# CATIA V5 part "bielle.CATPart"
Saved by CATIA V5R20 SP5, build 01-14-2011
Part number: bielle
Publications: "epaisseur"
Bounding box of the stored display mesh (mm): x -125 to 350, y 175.015 to 450.797, z 445 to 928.333
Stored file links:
  F:\iao fini\bielle.CATPart
  F:\iao fini\iao-finipbgliss.CATProduct
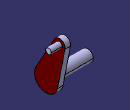
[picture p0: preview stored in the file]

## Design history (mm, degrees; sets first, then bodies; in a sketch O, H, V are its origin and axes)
Parameters
  epaisseur = 50 mm
External parameters (linked from other documents)
  External.rayontrou = 50 mm
  External.epaisseur = 125 mm
Set1
  Plane1 "Planbielle": linked copy from another document
  Point1 "Abis": linked copy from another document
  Point2: linked copy from another document
Body1 (main body)
  Sketch1 on Plane1, origin (200, 0, 0), H (0, 1, 0), V (0, 0, 1)
    arc A1 centre (400.9199, 878.4484) radius 49.8847 from (449.8633, 868.8035) to (357.4062, 902.842) ccw
    point P1 (400.9199, 878.4484)
    arc A2 centre (280, 550) radius 105.019 from (188.3935, 601.3542) to (383.0374, 529.6951) ccw
    point P2 (280, 550)
    reference projected point E1 (280, 550) from Point1
    reference projected point E2 (400.9199, 878.4484) from Point2
    line L1 (383.0374, 529.6951) -> (449.8633, 868.8035)
    line L2 (357.4062, 902.842) -> (188.3935, 601.3542)
    coincidence: E1 P2, P1 E2
    tangency: L1 A1, A2 L1, L2 A2, A1 L2
  Pad1: profile Sketch1, direction (1, 0, 0), length 50 {= epaisseur}
  Sketch2 on start face of Pad1, origin (200, 0, 0), H (0, -1, 0), V (0, 0, 1)
    circle A1 centre (-280, 550) radius 50
    point P1 (-280, 550)
    reference projected point E1 (-280, 550) from Point1
    radius A1 = 50 {= External.rayontrou}
    coincidence: P1 E1
  Pad2: profile Sketch2, direction (-1, 0, 0), length 325 {= External.epaisseur +epaisseur*4}
  Sketch3 on end face of Pad1, origin (250, 0, 0), H (0, 1, 0), V (0, 0, 1)
    circle A1 centre (400.9199, 878.4484) radius 25
    point P1 (400.9199, 878.4484)
    reference projected point E1 (400.9199, 878.4484) from Point2
    radius A1 = 25 {= 1/2*External.rayontrou}
    coincidence: E1 P1
  Pad3: profile Sketch3, direction (1, 0, 0), length 100 {= epaisseur *2}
